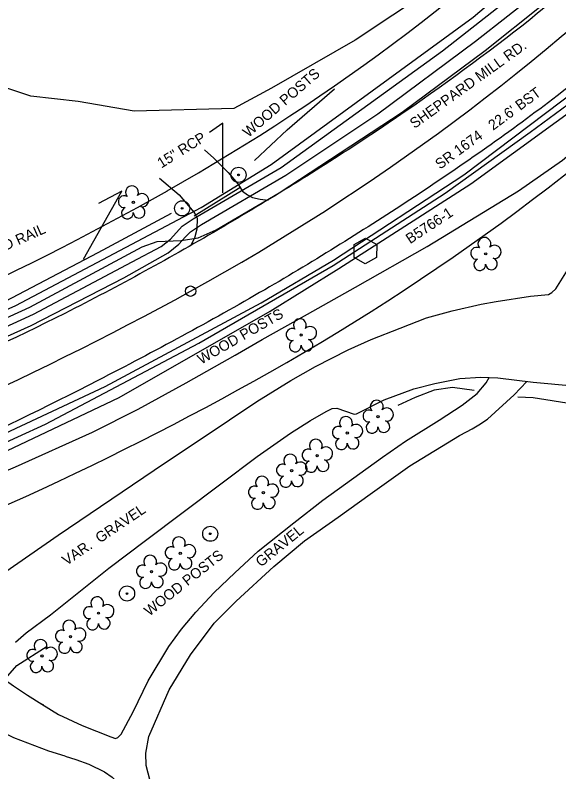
# Model space of a CAD drawing. Extents: x 1645945 to 2447332, y 713118 to 970361.
# Drawn here: x 1647397.4 to 1647554, y 969519.4 to 969737.2 of the extents above; entities that cross this region are included whole.
import ezdxf

# ---------------------------------------------------------------- set-up
doc = ezdxf.new("R2010")
doc.units = 0
for name, color, linetype in [('CTL Primary Horizontal and Vertical CELL', 7, 'Continuous'), ('CTL Primary Horizontal and Vertical Text', 7, 'Continuous'), ('Exist Horizontal Alignment', 7, 'Continuous'), ('Exist Horizontal Alignment Station Label', 7, 'Continuous'), ('Exist Other Culture Area Outline', 7, 'Continuous'), ('Exist Other Culture Area Outline Text', 7, 'Continuous'), ('Exist Other Culture Fence Line', 7, 'Continuous'), ('Exist Other Culture Fence Line Leader', 7, 'Continuous'), ('Exist Other Culture Fence Line Text', 7, 'Continuous'), ('Exist Other Culture Located Object CELL', 7, 'Continuous'), ('Exist Other Culture Located Object Text', 7, 'Continuous'), ('Exist Right of Way Line', 7, 'Continuous'), ('Exist Roads EOP', 7, 'Continuous'), ('Exist Roads EOP Text', 7, 'Continuous'), ('Exist Roads Soil', 7, 'Continuous'), ('Exist Roads Soil Text', 7, 'Continuous'), ('Exist Structure Minor Pipes RCP 15 Inch', 7, 'Continuous'), ('Exist Structure Minor Pipes RCP 15 Inch Leader', 7, 'Continuous'), ('Exist Structure Minor Pipes RCP 15 Inch Text', 7, 'Continuous'), ('Exist Utilities Sanitary Sewer Forced Main SUE LOS B', 7, 'Continuous'), ('Exist Utilities Telephone UG Cable SUE LOS C', 7, 'Continuous'), ('Exist Utilities Telephone UG Conduit SUE LOS B', 7, 'Continuous'), ('Exist Utilities Telephone UG FO SUE LOS C', 7, 'Continuous'), ('Exist Vegetation Tree CELL', 7, 'Continuous'), ('Exist Vegetation Woods Line', 7, 'Continuous')]:
    doc.layers.add(name, color=color, linetype=linetype)

msp = doc.modelspace()

# ---------------------------------------------------------------- linework, layer by layer
at = {"layer": 'CTL Primary Horizontal and Vertical CELL'}
msp.add_line((1647498.28, 969669.33), (1647498.28, 969669.33), dxfattribs=at)
msp.add_lwpolyline([(1647495.05, 969671.2), (1647498.3, 969673.02), (1647501.55, 969671.23), (1647501.5, 969667.5), (1647498.25, 969665.62), (1647495.05, 969667.43)], close=True, dxfattribs=at)
at = {"layer": 'Exist Horizontal Alignment'}
for centre, radius, start, end in [((1647126.83, 970240.1), 665, 298.87121, 329.93673), ((1647013.36, 970445.89), 900, 278.18107, 298.87121)]:
    msp.add_arc(centre, radius, start, end, dxfattribs=at)
at = {"layer": 'Exist Horizontal Alignment Station Label'}
msp.add_circle((1647447.92, 969657.76), 1.5, dxfattribs=at)
at = {"layer": 'Exist Other Culture Area Outline'}
for points in [[(1647405.68, 969538.55), (1647405.12, 969538.89), (1647409.93, 969535.85), (1647416.73, 969532.75), (1647424.97, 969529.43), (1647426.31, 969528.98), (1647426.96, 969529.24), (1647427.89, 969530.21), (1647431.37, 969536.62), (1647435.75, 969545.53), (1647441.69, 969555.47), (1647445.35, 969560.48), (1647449.46, 969565.35), (1647454.76, 969571.02), (1647460.72, 969576.69), (1647467.44, 969582.9), (1647477.7, 969591.06), (1647485.99, 969597.55), (1647503.25, 969609.93), (1647509.83, 969614.55), (1647519.52, 969620.58), (1647526.19, 969624.93), (1647530.51, 969628.27), (1647533.11, 969631.37), (1647533.9, 969632.86)], [(1647439.87, 969508.1), (1647438.49, 969509.86), (1647437.54, 969512.01), (1647435.11, 969521.22), (1647435.07, 969524.72), (1647435.92, 969529.56), (1647441.73, 969543.01), (1647447.88, 969553.1), (1647454.77, 969562.17), (1647461.05, 969568.53), (1647471.91, 969578.46), (1647480.74, 969585.91), (1647490.45, 969592.68), (1647499.65, 969599.36), (1647511.11, 969607.52), (1647525.4, 969616.25), (1647527.38, 969617.29), (1647529.05, 969618.11), (1647530.96, 969619.24), (1647533.48, 969620.89), (1647541.13, 969627.92), (1647544.79, 969631.78)], [(1647411.84, 969523.84), (1647407.07, 969525.32), (1647396.98, 969529.18), (1647388.81, 969533.3), (1647383.02, 969536.31), (1647394.64, 969545.72), (1647396.91, 969544.16), (1647400.94, 969541.47), (1647405.12, 969538.89)], [(1647411.84, 969523.84), (1647414.86, 969522.9), (1647418.59, 969521.6), (1647423.11, 969519.34), (1647425.34, 969517.88), (1647426.47, 969516.67), (1647427.19, 969515.06), (1647431.49, 969505.44), (1647433.32, 969503.03), (1647435.41, 969500.48)]]:
    msp.add_lwpolyline(points, dxfattribs=at)
at = {"layer": 'Exist Other Culture Fence Line'}
for points in [[(1647378.48, 969599.04), (1647397.5, 969607.19), (1647419.7, 969617.12), (1647432.85, 969623.77), (1647446.7, 969631.34), (1647460.79, 969639.34), (1647468.57, 969643.81), (1647481.65, 969651.11), (1647495.44, 969658.93), (1647516.04, 969670.64), (1647542.37, 969686.67), (1647555.03, 969695.43), (1647566.23, 969704.89), (1647576.04, 969713.96), (1647601.68, 969736.14), (1647620.49, 969754.94)], [(1647466.33, 969695.42), (1647475.76, 969704.18), (1647489.41, 969716.01)], [(1647360.31, 969639.7), (1647378.33, 969647.09), (1647392.53, 969653.79), (1647421.31, 969668.92), (1647442.47, 969680.24)], [(1647529.66, 969629.18), (1647523.42, 969630.04), (1647518.07, 969629.26), (1647512.63, 969627.11), (1647507.61, 969624.88)], [(1647635.19, 969613.46), (1647607.02, 969617.47), (1647595.33, 969619.52), (1647567.81, 969623.73), (1647546.62, 969627.01), (1647542.22, 969627.22)], [(1647382.35, 969536.58), (1647387.97, 969540.94), (1647394.64, 969546.24), (1647397.88, 969549.96), (1647406.66, 969555.58)]]:
    msp.add_lwpolyline(points, dxfattribs=at)
at = {"layer": 'Exist Other Culture Fence Line Leader'}
msp.add_lwpolyline([(1647417.08, 969667.02), (1647428.16, 969686.55), (1647421.38, 969683.03)], dxfattribs=at)
at = {"layer": 'Exist Other Culture Located Object CELL'}
for centre, radius in [((1647461.75, 969691.24), 2.18), ((1647461.75, 969691.24), 0.24), ((1647445.49, 969681.6), 2.18), ((1647445.49, 969681.6), 0.24), ((1647453.59, 969587.92), 2.18), ((1647453.59, 969587.92), 0.24), ((1647429.63, 969570.71), 2.18), ((1647429.63, 969570.71), 0.24)]:
    msp.add_circle(centre, radius, dxfattribs=at)
at = {"layer": 'Exist Right of Way Line'}
for centre, radius, start, end in [((1647136.28, 970226.5), 620, 299.46236, 329.93673), ((1647136.28, 970226.5), 680, 299.46236, 329.93673), ((1647025.62, 970422.4), 845, 278.18107, 299.46236), ((1647025.62, 970422.4), 905, 278.18107, 299.46236)]:
    msp.add_arc(centre, radius, start, end, dxfattribs=at)
at = {"layer": 'Exist Roads EOP'}
for points in [[(1647712.71, 969946.05), (1647689.83, 969906.56), (1647665.85, 969869.13), (1647637.34, 969829.12), (1647607.92, 969794.57), (1647574.53, 969760.72), (1647538.69, 969730.5), (1647499.85, 969702.79), (1647457.34, 969676.33), (1647411.66, 969651.37), (1647366.8, 969630.41), (1647321.37, 969611.83), (1647279.28, 969597.97), (1647224.82, 969583.15), (1647179.92, 969574.15), (1647132.17, 969565.53), (1647083.22, 969557.97), (1647036.22, 969550.58), (1646989.26, 969543.73)], [(1647731.3, 969935.45), (1647707.71, 969895.07), (1647684.27, 969857.13), (1647654.38, 969814.5), (1647624.46, 969779.25), (1647589.97, 969744.66), (1647553.5, 969714.01), (1647512.43, 969684.95), (1647469.3, 969658.19), (1647421.26, 969632.07), (1647375.68, 969609.9), (1647329.15, 969590.49), (1647286.02, 969576.26), (1647230.19, 969561.18), (1647183.04, 969552.75), (1647135.89, 969544.58), (1647086.4, 969536.99), (1647040.14, 969529.53), (1646992.05, 969522.32)]]:
    msp.add_spline(points, degree=3, dxfattribs=at)
at = {"layer": 'Exist Roads Soil'}
for points in [[(1647451.92, 969698.48), (1647454.64, 969696.1), (1647458.76, 969691.95), (1647461.51, 969688.63), (1647462.13, 969687.72), (1647462.88, 969686.57), (1647464.37, 969685.47), (1647465.81, 969684.76), (1647468.02, 969684.21), (1647470.32, 969683.94)], [(1647439.02, 969690.27), (1647444.64, 969685.47), (1647448.87, 969680.46), (1647449.34, 969679.74), (1647449.83, 969678.77), (1647449.7, 969675.6), (1647449.1, 969673.05), (1647448.01, 969670.97)], [(1647389.89, 969573.75), (1647409.76, 969587.55), (1647437.43, 969606.18), (1647459.13, 969620.72), (1647467.03, 969625.99), (1647476.84, 969632.04), (1647483.95, 969636.05), (1647493.34, 969640.91), (1647499.96, 969643.81), (1647508.28, 969647.15), (1647515.88, 969650.1), (1647523.28, 969652.1), (1647531.66, 969654.03), (1647535.94, 969654.81), (1647545.88, 969656.29), (1647551.02, 969656.8), (1647552.03, 969657.34), (1647553.18, 969658.4), (1647559.42, 969668.42)], [(1647397.48, 969556.7), (1647400.55, 969559.4), (1647407.57, 969564.57), (1647424.42, 969577.97), (1647434.96, 969586), (1647456.6, 969602.26), (1647467.07, 969610.12), (1647476.67, 969616.84), (1647482.5, 969620.5), (1647486.94, 969623.15), (1647488.75, 969623.98), (1647490.1, 969624.11), (1647495.05, 969622.31), (1647495.71, 969622.45), (1647503.72, 969626.47), (1647512.26, 969629.62), (1647518.33, 969631.15), (1647525.52, 969632.58), (1647531.57, 969633.05), (1647536.43, 969632.77), (1647546.63, 969631.57), (1647569.68, 969629.41)]]:
    msp.add_lwpolyline(points, dxfattribs=at)
at = {"layer": 'Exist Structure Minor Pipes RCP 15 Inch'}
msp.add_line((1647448.95, 969679.47), (1647462.38, 969687.82), dxfattribs=at)
at = {"layer": 'Exist Structure Minor Pipes RCP 15 Inch Leader'}
msp.add_lwpolyline([(1647457.19, 969686.08), (1647457.21, 969706.1), (1647453.42, 969703.47)], dxfattribs=at)
at = {"layer": 'Exist Utilities Sanitary Sewer Forced Main SUE LOS B'}
msp.add_lwpolyline([(1647281.82, 969570.96), (1647301.43, 969576.57), (1647317.63, 969582.51), (1647339.14, 969590.95), (1647371.77, 969606.21), (1647423.35, 969630.3), (1647468.23, 969654.45), (1647489.07, 969666.65), (1647526.6, 969691.29), (1647564.25, 969719.63), (1647582.69, 969734.56), (1647601.35, 969752.36), (1647608.99, 969759.23), (1647621.71, 969772.62)], dxfattribs=at)
at = {"layer": 'Exist Utilities Telephone UG Cable SUE LOS C'}
for points in [[(1647301.18, 969607.49), (1647346.35, 969625.33), (1647402.72, 969651.12), (1647431.08, 969666.24), (1647439.41, 969670.62), (1647442.16, 969672.78), (1647445.5, 969676.48), (1647448.63, 969678.56), (1647474.06, 969693.41), (1647520.52, 969726.92), (1647556, 969754.87), (1647590.11, 969785.42), (1647617.35, 969813.54), (1647647.46, 969852.3), (1647702.67, 969945.18), (1647775.84, 970087.47)], [(1647299.74, 969604.87), (1647344.43, 969621.93), (1647402.05, 969647.91), (1647428.7, 969661.61), (1647441.47, 969668.79), (1647444.57, 969671.27), (1647446.47, 969673.44), (1647447.93, 969674.84), (1647451.1, 969676.98), (1647475.41, 969691.19), (1647501.84, 969708.82), (1647529.96, 969729.71), (1647548.6, 969744.41), (1647576.21, 969768.81), (1647599.16, 969791.2), (1647624.94, 969819.94), (1647649.96, 969852.56), (1647680.88, 969902.23), (1647705.82, 969944.72), (1647779.36, 970085.84)], [(1647294.11, 969544.68), (1647330.92, 969585.92), (1647342.26, 969590.26), (1647406.15, 969619.43), (1647450.3, 969642.78), (1647488.96, 969665.16), (1647521.25, 969685.99), (1647545.76, 969703.5), (1647563.98, 969716.93), (1647573.87, 969725.16), (1647593.32, 969742.95), (1647627.6, 969780.32), (1647655.82, 969815.07), (1647672.99, 969839.14), (1647691.44, 969867.28), (1647722.34, 969918.27), (1647755.1, 969977.16), (1647804.4, 970074.3)]]:
    msp.add_lwpolyline(points, dxfattribs=at)
at = {"layer": 'Exist Utilities Telephone UG Conduit SUE LOS B'}
msp.add_lwpolyline([(1647288.65, 969579.3), (1647300.87, 969579.36), (1647319.33, 969581.75), (1647340.65, 969587.35), (1647374.06, 969601.91), (1647427.36, 969627.15), (1647470.88, 969652.02), (1647490.61, 969664.32), (1647528.7, 969688.64), (1647565.5, 969715.45)], dxfattribs=at)
at = {"layer": 'Exist Utilities Telephone UG FO SUE LOS C'}
for points in [[(1647289.7, 969609.34), (1647343.59, 969629.58), (1647397.62, 969653.63), (1647450.96, 969681.88), (1647471.14, 969694.21), (1647529.28, 969736.65), (1647578.89, 969778.78), (1647616.07, 969816.36), (1647645.02, 969855.2), (1647696.33, 969943.83), (1647771.33, 970089.55)], [(1647291.19, 969605.96), (1647345.09, 969627.35), (1647401.66, 969653.17), (1647434.03, 969670.53), (1647438.26, 969672.06), (1647445.18, 969672.38), (1647450.09, 969673.09), (1647455.34, 969675.46), (1647473.43, 969686.09), (1647508.86, 969709.29), (1647532.76, 969727.04), (1647549.35, 969740.28), (1647575.78, 969764.21), (1647609.03, 969797.83), (1647638.13, 969832.64), (1647665.39, 969871.17), (1647698.7, 969925.68), (1647740.76, 970001.75), (1647782.56, 970084.37)]]:
    msp.add_lwpolyline(points, dxfattribs=at)
at = {"layer": 'Exist Vegetation Tree CELL'}
for p, q in [((1647431.44, 969683.37), (1647431.44, 969683.37)), ((1647532.94, 969668.51), (1647532.94, 969668.51)), ((1647479.78, 969645.11), (1647479.78, 969645.11)), ((1647501.93, 969621.66), (1647501.93, 969621.66)), ((1647493.08, 969616.92), (1647493.08, 969616.92)), ((1647484.39, 969610.42), (1647484.39, 969610.42)), ((1647477.03, 969606.09), (1647477.03, 969606.09)), ((1647468.91, 969599.74), (1647468.91, 969599.74)), ((1647444.95, 969582.31), (1647444.95, 969582.31)), ((1647436.67, 969577), (1647436.67, 969577)), ((1647421.4, 969565.06), (1647421.4, 969565.06)), ((1647413.34, 969558.28), (1647413.34, 969558.28)), ((1647405.11, 969552.76), (1647405.11, 969552.76))]:
    msp.add_line(p, q, dxfattribs=at)
for centre in [(1647431.44, 969683.37), (1647532.94, 969668.51), (1647479.78, 969645.11), (1647501.93, 969621.66), (1647493.08, 969616.92), (1647484.39, 969610.42), (1647477.03, 969606.09), (1647468.91, 969599.74), (1647444.95, 969582.31), (1647436.67, 969577), (1647421.4, 969565.06), (1647413.34, 969558.28), (1647405.11, 969552.76)]:
    msp.add_circle(centre, 0.326, dxfattribs=at)
for centre, radius, start, end in [((1647431.05, 969686.24), 1.86, 330.1651, 219.7134), ((1647428.83, 969683.52), 1.73, 62.6636, 279.3457), ((1647433.98, 969683.96), 1.9, 257.1011, 134.1999), ((1647429.73, 969680.25), 1.69, 111.5671, 6.231), ((1647433.11, 969680.47), 1.7, 181.2822, 74.56), ((1647532.56, 969671.38), 1.86, 330.1651, 219.7134), ((1647530.34, 969668.66), 1.73, 62.6636, 279.3457), ((1647535.49, 969669.1), 1.9, 257.1011, 134.1999), ((1647534.61, 969665.61), 1.7, 181.2822, 74.56), ((1647531.24, 969665.39), 1.69, 111.5671, 6.231), ((1647479.4, 969647.98), 1.86, 330.1651, 219.7134), ((1647482.33, 969645.7), 1.9, 257.1011, 134.1999), ((1647477.17, 969645.26), 1.73, 62.6636, 279.3457), ((1647478.08, 969641.99), 1.69, 111.5671, 6.231), ((1647481.45, 969642.21), 1.7, 181.2822, 74.56), ((1647501.54, 969624.54), 1.86, 330.1651, 219.7134), ((1647499.32, 969621.82), 1.73, 62.6636, 279.3457), ((1647504.48, 969622.25), 1.9, 257.1011, 134.1999), ((1647492.69, 969619.79), 1.86, 330.1651, 219.7134), ((1647495.63, 969617.51), 1.9, 257.1011, 134.1999), ((1647500.22, 969618.54), 1.69, 111.5671, 6.231), ((1647503.6, 969618.76), 1.7, 181.2822, 74.56), ((1647490.47, 969617.07), 1.73, 62.6636, 279.3457), ((1647484.01, 969613.29), 1.86, 330.1651, 219.7134), ((1647491.38, 969613.8), 1.69, 111.5671, 6.231), ((1647494.75, 969614.02), 1.7, 181.2822, 74.56), ((1647486.94, 969611.01), 1.9, 257.1011, 134.1999), ((1647476.65, 969608.96), 1.86, 330.1651, 219.7134), ((1647481.79, 969610.57), 1.73, 62.6636, 279.3457), ((1647479.58, 969606.68), 1.9, 257.1011, 134.1999), ((1647482.69, 969607.3), 1.69, 111.5671, 6.231), ((1647486.06, 969607.52), 1.7, 181.2822, 74.56), ((1647474.43, 969606.24), 1.73, 62.6636, 279.3457), ((1647468.52, 969602.61), 1.86, 330.1651, 219.7134), ((1647475.33, 969602.97), 1.69, 111.5671, 6.231), ((1647478.71, 969603.19), 1.7, 181.2822, 74.56), ((1647466.3, 969599.89), 1.73, 62.6636, 279.3457), ((1647471.45, 969600.33), 1.9, 257.1011, 134.1999), ((1647467.2, 969596.62), 1.69, 111.5671, 6.231), ((1647470.58, 969596.84), 1.7, 181.2822, 74.56), ((1647444.57, 969585.18), 1.86, 330.1651, 219.7134), ((1647447.5, 969582.9), 1.9, 257.1011, 134.1999), ((1647442.35, 969582.46), 1.73, 62.6636, 279.3457), ((1647436.29, 969579.87), 1.86, 330.1651, 219.7134), ((1647443.25, 969579.19), 1.69, 111.5671, 6.231), ((1647446.63, 969579.41), 1.7, 181.2822, 74.56), ((1647434.07, 969577.15), 1.73, 62.6636, 279.3457), ((1647439.22, 969577.58), 1.9, 257.1011, 134.1999), ((1647438.35, 969574.1), 1.7, 181.2822, 74.56), ((1647434.97, 969573.87), 1.69, 111.5671, 6.231), ((1647421.02, 969567.93), 1.86, 330.1651, 219.7134), ((1647418.8, 969565.21), 1.73, 62.6636, 279.3457), ((1647423.95, 969565.65), 1.9, 257.1011, 134.1999), ((1647412.96, 969561.15), 1.86, 330.1651, 219.7134), ((1647419.7, 969561.94), 1.69, 111.5671, 6.231), ((1647423.07, 969562.16), 1.7, 181.2822, 74.56), ((1647415.89, 969558.87), 1.9, 257.1011, 134.1999), ((1647410.74, 969558.43), 1.73, 62.6636, 279.3457), ((1647404.73, 969555.63), 1.86, 330.1651, 219.7134), ((1647411.64, 969555.16), 1.69, 111.5671, 6.231), ((1647415.01, 969555.38), 1.7, 181.2822, 74.56), ((1647402.51, 969552.91), 1.73, 62.6636, 279.3457), ((1647407.66, 969553.35), 1.9, 257.1011, 134.1999), ((1647403.41, 969549.64), 1.69, 111.5671, 6.231), ((1647406.79, 969549.86), 1.7, 181.2822, 74.56)]:
    msp.add_arc(centre, radius, start, end, dxfattribs=at)
at = {"layer": 'Exist Vegetation Woods Line'}
msp.add_lwpolyline([(1647517.03, 969744.5), (1647495.35, 969729.99), (1647471.19, 969716.25), (1647460.39, 969710.38), (1647431.64, 969709.61), (1647415.55, 969712.4), (1647401.93, 969713.9), (1647395.29, 969716.09), (1647374.09, 969725.56), (1647339.04, 969715.08), (1647303.79, 969706.09), (1647302.25, 969707.44), (1647299.84, 969713.9), (1647295.54, 969715.64), (1647292.3, 969714.45), (1647288.08, 969706.3), (1647285.4, 969706.33), (1647270.06, 969708.07), (1647265.52, 969709.48), (1647237.13, 969734.31), (1647228.98, 969743.77)], dxfattribs=at)

# ---------------------------------------------------------------- texts
at = {"layer": 'CTL Primary Horizontal and Vertical Text'}
msp.add_text('B5766-1', height=3, rotation=33.452, dxfattribs=at).set_placement((1647511.16, 969671.26))
at = {"layer": 'Exist Other Culture Area Outline Text'}
msp.add_text('GRAVEL', height=3, rotation=39.0466, dxfattribs=at).set_placement((1647468.18, 969578.18))
at = {"layer": 'Exist Other Culture Fence Line Text'}
for s, rotation, p in [('WOOD POSTS', 40.9224, (1647464.56, 969701.86)), ('WOOD POSTS W/ WOOD RAIL', 23.9539, (1647353.71, 969651.19)), ('WOOD POSTS', 29.8737, (1647451, 969636.6))]:
    msp.add_text(s, height=3, rotation=rotation, dxfattribs=at).set_placement(p)
at = {"layer": 'Exist Other Culture Located Object Text'}
msp.add_text('WOOD POSTS', height=3, rotation=38.3846, dxfattribs=at).set_placement((1647436.04, 969564.04))
at = {"layer": 'Exist Roads EOP Text'}
for s, rotation, p in [('SHEPPARD MILL RD.', 35.6893, (1647512.44, 969704.44)), ("SR 1674   22.6' BST", 36.2763, (1647519.77, 969692.71))]:
    msp.add_text(s, height=3, rotation=rotation, dxfattribs=at).set_placement(p)
at = {"layer": 'Exist Roads Soil Text'}
msp.add_text('VAR.  GRAVEL', height=3, rotation=33.9487, dxfattribs=at).set_placement((1647412.18, 969578.65))
at = {"layer": 'Exist Structure Minor Pipes RCP 15 Inch Text'}
msp.add_text('15" RCP', height=3, rotation=31.8745, dxfattribs=at).set_placement((1647439.51, 969693.05))

doc.saveas('drawing.dxf')
